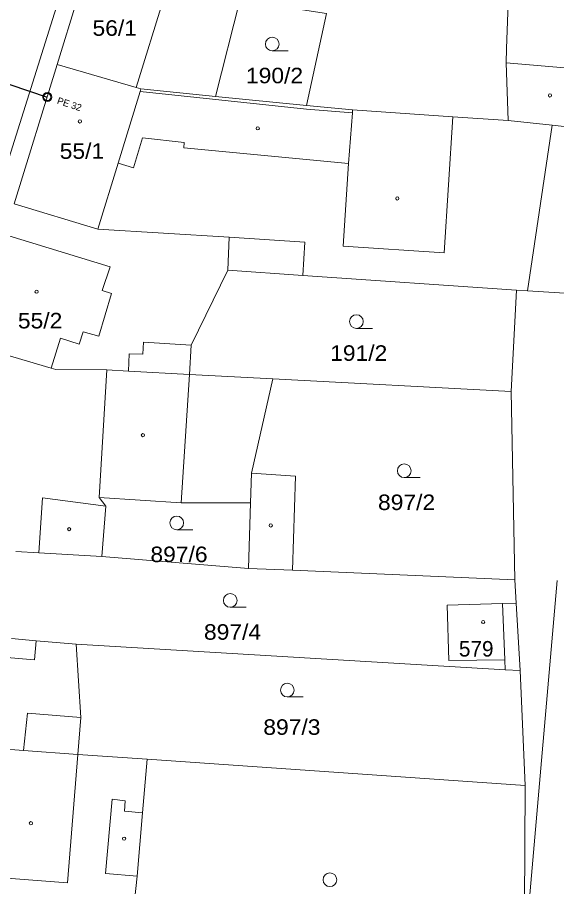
# Model space of a CAD drawing. Extents: x -686207 to -681951, y -1020493 to -1017811.
# Drawn here: x -682452.2 to -682393.2, y -1019020.1 to -1018924.9 of the extents above; entities that cross this region are included whole.
import ezdxf
from ezdxf.enums import TextEntityAlignment as Align

# ---------------------------------------------------------------- set-up
doc = ezdxf.new("R2010")
doc.units = 0
doc.header["$LTSCALE"] = 0.4
doc.linetypes.add('LONG_DASHED', pattern=[7.5, 6, -1.5])
for name, color, linetype, lineweight in [('1', 7, 'Continuous', 13), ('12', 7, 'Continuous', 13), ('3', 7, 'Continuous', 13), ('4', 7, 'Continuous', 13), ('5', 7, 'Continuous', 13), ('50', 7, 'LONG_DASHED', 25)]:
    doc.layers.add(name, color=color, linetype=linetype, lineweight=lineweight)
doc.layers.add('19', color=7, linetype='Continuous')
doc.layers.add('2', color=7, linetype='Continuous')

msp = doc.modelspace()

# ---------------------------------------------------------------- linework, layer by layer
at = {"layer": '1'}
for p, q in [((-682443.15, -1018914.58), (-682447.88, -1018930.08)), ((-682430.56, -1018933.56), (-682427.89, -1018923.06)), ((-682420.6, -1018934.55), (-682430.56, -1018933.56)), ((-682393.69, -1018936.72), (-682398.48, -1018936.22)), ((-682396.38, -1018954.85), (-682393.69, -1018936.72)), ((-682393.69, -1018936.72), (-682389.52, -1018937.15)), ((-682420.97, -1018953.18), (-682397.57, -1018954.78)), ((-682398.16, -1018965.88), (-682397.57, -1018954.78)), ((-682397.57, -1018954.78), (-682396.38, -1018954.85)), ((-682424.27, -1018964.49), (-682398.16, -1018965.88)), ((-682398.16, -1018965.88), (-682397.77, -1018986.51)), ((-682426.94, -1018985.24), (-682443, -1018983.96)), ((-682397.17, -1018996.44), (-682397.62, -1018989.05)), ((-682452.9, -1018992.92), (-682450.18, -1018993.16)), ((-682397.17, -1018996.44), (-682396.64, -1019009.02)), ((-682396.64, -1019009.02), (-682438.05, -1019006.15)), ((-682396.64, -1019009.02), (-682396.76, -1019028.35))]:
    msp.add_line(p, q, dxfattribs=at)
for points in [[(-682426.07, -1018859.13), (-682426.87, -1018859.15), (-682427.6, -1018859.49), (-682428.08, -1018860.21), (-682439.62, -1018897.1), (-682465.76, -1018980.32)], [(-682396.77, -1018892.81), (-682397.47, -1018895.81), (-682398.69, -1018928.32), (-682398.7, -1018929.89), (-682398.48, -1018936.22)], [(-682424.35, -1018923.59), (-682418.39, -1018924.49), (-682420.6, -1018934.55)], [(-682430.56, -1018933.56), (-682438.73, -1018932.75), (-682439.23, -1018932.6), (-682447.88, -1018930.08), (-682452.58, -1018945.34)], [(-682398.48, -1018936.22), (-682404.55, -1018935.79), (-682415.54, -1018935.05), (-682420.6, -1018934.55)], [(-682389.52, -1018937.15), (-682391.12, -1018955.18), (-682396.38, -1018954.85)], [(-682452.58, -1018945.34), (-682443.44, -1018948.1), (-682429.05, -1018948.99), (-682420.77, -1018949.51), (-682420.97, -1018953.18)], [(-682433.41, -1018964), (-682433.21, -1018960.82), (-682429.2, -1018952.58), (-682420.97, -1018953.18)], [(-682457.34, -1018960.73), (-682448.55, -1018963.31), (-682448.02, -1018963.47), (-682442.44, -1018963.52), (-682440.09, -1018963.65), (-682433.41, -1018964)], [(-682422.11, -1018985.45), (-682421.79, -1018975.15), (-682426.61, -1018974.83), (-682424.27, -1018964.49), (-682433.41, -1018964)], [(-682443, -1018983.96), (-682442.56, -1018978.44), (-682443.3, -1018977.5), (-682434.3, -1018978.05), (-682426.71, -1018978.07), (-682426.94, -1018985.24), (-682422.11, -1018985.45)], [(-682452.4, -1018983.4), (-682449.88, -1018983.55), (-682443, -1018983.96)], [(-682422.11, -1018985.45), (-682397.77, -1018986.51), (-682397.62, -1018989.05)], [(-682397.62, -1018989.05), (-682399.12, -1018989.09), (-682405.17, -1018989.27), (-682404.99, -1018995.33), (-682398.87, -1018995.26), (-682398.82, -1018996.34), (-682397.17, -1018996.44)], [(-682450.18, -1018993.16), (-682450.36, -1018995.25), (-682453.39, -1018994.99), (-682453.91, -1018997.98), (-682454.51, -1018997.88), (-682457.25, -1019003.19)], [(-682398.82, -1018996.34), (-682445.81, -1018993.53), (-682450.18, -1018993.16)], [(-682457.25, -1019003.19), (-682457.89, -1019004.44), (-682454.51, -1019004.97), (-682451.58, -1019005.17), (-682445.62, -1019005.63), (-682438.05, -1019006.15)], [(-682438.05, -1019006.15), (-682438.55, -1019012.01), (-682439.14, -1019018.93), (-682440.04, -1019027.37), (-682457.63, -1019022.56), (-682474.62, -1019017.33)]]:
    msp.add_lwpolyline(points, dxfattribs=at)
at = {"layer": '12'}
for radius in [0.5, 0.4]:
    msp.add_circle((-682448.974, -1018933.632), radius, dxfattribs=at)
at = {"layer": '3'}
for p, q in [((-682424.333, -1018928.58), (-682422.583, -1018928.58)), ((-682415.113, -1018958.97), (-682413.363, -1018958.97)), ((-682409.873, -1018975.31), (-682408.123, -1018975.31)), ((-682434.793, -1018981.01), (-682433.043, -1018981.01)), ((-682428.933, -1018989.51), (-682427.183, -1018989.51)), ((-682422.683, -1018999.32), (-682420.933, -1018999.32))]:
    msp.add_line(p, q, dxfattribs=at)
for centre in [(-682424.3329, -1018927.8298), (-682415.1129, -1018958.2198), (-682409.8729, -1018974.5598), (-682434.7929, -1018980.2598), (-682428.9329, -1018988.7598), (-682422.6829, -1018998.5698), (-682418.0129, -1019019.3398)]:
    msp.add_circle(centre, 0.75, dxfattribs=at)
at = {"layer": '4'}
for p, q in [((-682439.23, -1018932.6), (-682434.55, -1018917.38)), ((-682398.7, -1018929.89), (-682388.95, -1018930.73)), ((-682441.19, -1018940.89), (-682438.81, -1018933.04)), ((-682438.81, -1018933.04), (-682438.73, -1018932.75)), ((-682438.81, -1018933.04), (-682434.3, -1018933.51)), ((-682434.3, -1018933.51), (-682420.58, -1018934.95)), ((-682420.58, -1018934.95), (-682415.56, -1018935.35)), ((-682405.5, -1018950.71), (-682404.55, -1018935.79)), ((-682439.52, -1018941.38), (-682438.53, -1018938.12)), ((-682438.53, -1018938.12), (-682433.97, -1018938.61)), ((-682434.02, -1018939.21), (-682433.97, -1018938.61)), ((-682434.02, -1018939.21), (-682415.98, -1018940.91)), ((-682443.44, -1018948.1), (-682441.19, -1018940.89)), ((-682441.19, -1018940.89), (-682439.52, -1018941.38)), ((-682416.56, -1018949.98), (-682415.98, -1018940.91)), ((-682453.67, -1018948.67), (-682442.1, -1018952.21)), ((-682429.2, -1018952.58), (-682429.05, -1018948.99)), ((-682416.56, -1018949.98), (-682405.5, -1018950.71)), ((-682442.97, -1018954.81), (-682442.1, -1018952.21)), ((-682443.31, -1018959.83), (-682441.94, -1018955.15)), ((-682442.97, -1018954.81), (-682441.94, -1018955.15)), ((-682445.48, -1018960.68), (-682445.05, -1018959.33)), ((-682445.05, -1018959.33), (-682443.31, -1018959.83)), ((-682448.55, -1018963.31), (-682447.52, -1018960.03)), ((-682447.52, -1018960.03), (-682445.48, -1018960.68)), ((-682438.5, -1018961.8), (-682438.45, -1018960.47)), ((-682438.45, -1018960.47), (-682433.21, -1018960.82)), ((-682440.09, -1018963.65), (-682440, -1018961.74)), ((-682440, -1018961.74), (-682438.5, -1018961.8)), ((-682443.3, -1018977.5), (-682442.44, -1018963.52)), ((-682434.3, -1018978.05), (-682433.41, -1018964)), ((-682426.71, -1018978.07), (-682426.61, -1018974.83)), ((-682449.88, -1018983.55), (-682449.51, -1018977.53)), ((-682449.51, -1018977.53), (-682442.56, -1018978.44)), ((-682396.76, -1019028.35), (-682393.12, -1018986.59)), ((-682399.12, -1018989.09), (-682398.87, -1018995.26)), ((-682445.81, -1018993.53), (-682445.29, -1019001.58)), ((-682451.58, -1019005.17), (-682451.15, -1019001.1)), ((-682451.15, -1019001.1), (-682445.29, -1019001.58)), ((-682445.62, -1019005.63), (-682445.29, -1019001.58)), ((-682446.74, -1019019.69), (-682445.62, -1019005.63)), ((-682442.6, -1019018.64), (-682441.85, -1019010.51)), ((-682441.85, -1019010.51), (-682440.45, -1019010.69)), ((-682440.53, -1019011.84), (-682440.45, -1019010.69)), ((-682440.53, -1019011.84), (-682438.55, -1019012.01)), ((-682442.6, -1019018.64), (-682439.14, -1019018.93)), ((-682455.66, -1019018.99), (-682446.74, -1019019.69))]:
    msp.add_line(p, q, dxfattribs=at)
msp.add_lwpolyline([(-682415.98, -1018940.91), (-682415.56, -1018935.35), (-682415.54, -1018935.05)], dxfattribs=at)
at = {"layer": '5'}
for centre in [(-682393.9168, -1018933.4592), (-682445.3968, -1018936.3092), (-682425.9168, -1018937.0692), (-682410.6368, -1018944.7392), (-682450.1468, -1018954.9492), (-682438.4968, -1018970.6592), (-682446.5768, -1018980.9492), (-682424.4968, -1018980.5392), (-682401.2368, -1018991.1192), (-682450.7668, -1019013.1492), (-682440.5568, -1019014.8392)]:
    msp.add_circle(centre, 0.175, dxfattribs=at)
at = {"layer": '50', "linetype": 'Continuous'}
msp.add_lwpolyline([(-682457.56, -1018930.77), (-682457.08, -1018930.93), (-682448.974, -1018933.632)], dxfattribs=at)

# ---------------------------------------------------------------- texts
at = {"layer": '19'}
msp.add_text('PE 32', height=0.75, rotation=341.634, dxfattribs=at).set_placement((-682446.6652, -1018934.7702), align=Align.CENTER)
at = {"layer": '2', "width": 1.1}
for s, p in [('56/1', (-682444.021, -1018926.929)), ('190/2', (-682427.213, -1018932.13)), ('55/1', (-682447.611, -1018940.4)), ('55/2', (-682452.191, -1018958.97)), ('191/2', (-682417.993, -1018962.52)), ('897/2', (-682412.753, -1018978.86)), ('897/6', (-682437.673, -1018984.559)), ('897/4', (-682431.813, -1018993.059)), ('897/3', (-682425.313, -1019003.47))]:
    msp.add_text(s, height=1.7, dxfattribs=at).set_placement(p)
at = {"layer": '2'}
msp.add_text('579', height=1.7, dxfattribs=at).set_placement((-682403.894, -1018994.9))

doc.saveas('drawing.dxf')
